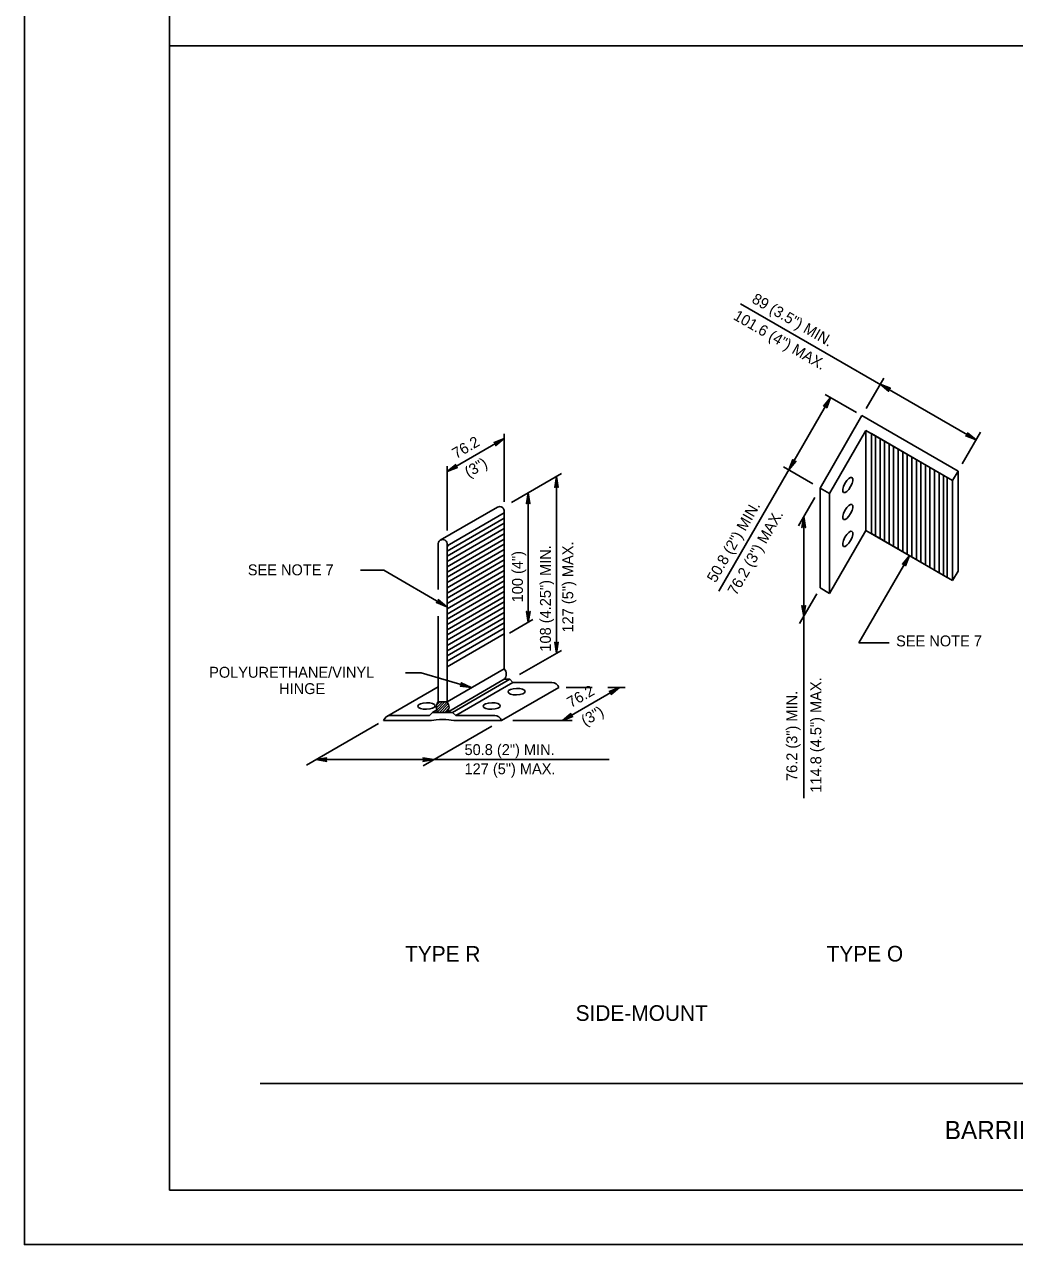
# Model space of a CAD drawing. Extents: x 640253 to 641999, y 298458 to 299646.
# Drawn here: x 640253.3 to 640526.1, y 298457.6 to 298793.5 of the extents above; entities that cross this region are included whole.
import ezdxf

# ---------------------------------------------------------------- set-up
doc = ezdxf.new("R2010")
doc.units = 0
for name, color, linetype in [('1', 7, 'Continuous'), ('2', 7, 'Continuous'), ('PLT-BNDY', 7, 'Continuous')]:
    doc.layers.add(name, color=color, linetype=linetype)

msp = doc.modelspace()

# ---------------------------------------------------------------- linework, layer by layer
at = {"layer": '1'}
for p, q in [((640293.31, 299036.63), (640293.31, 298472.63)), ((640293.31, 298787.67), (641079.31, 298787.67)), ((640318.26, 298501.97), (640782.88, 298501.97)), ((641079.31, 298472.63), (640293.31, 298472.63)), ((640293.31, 298472.63), (640879.31, 298472.63))]:
    msp.add_line(p, q, dxfattribs=at)
at = {"layer": '2'}
for p, q in [((640450.56, 298716.64), (640515.45, 298679.17)), ((640489.99, 298696.18), (640485.17, 298687.84)), ((640475.38, 298690.81), (640444.63, 298637.55)), ((640473.86, 298691.69), (640482.49, 298686.7)), ((640484.01, 298685.83), (640472.51, 298665.91)), ((640510.48, 298670.55), (640484.01, 298685.83)), ((640369.76, 298670.43), (640385.5, 298679.52)), ((640385.5, 298662.1), (640385.5, 298680.83)), ((640485.11, 298681.73), (640475.11, 298664.41)), ((640508.98, 298667.95), (640485.11, 298681.73)), ((640485.11, 298681.73), (640485.11, 298654.23)), ((640487.74, 298680.21), (640487.74, 298652.71)), ((640488.99, 298679.49), (640488.99, 298651.99)), ((640516.7, 298681.32), (640511.64, 298672.56)), ((640490.24, 298678.77), (640490.24, 298651.27)), ((640491.49, 298678.05), (640491.49, 298650.55)), ((640492.74, 298677.32), (640492.74, 298649.83)), ((640493.99, 298676.6), (640493.99, 298649.1)), ((640495.24, 298675.88), (640495.24, 298648.38)), ((640496.49, 298675.16), (640496.49, 298647.66)), ((640497.74, 298674.44), (640497.74, 298646.94)), ((640498.99, 298673.72), (640498.99, 298646.22)), ((640500.24, 298672.99), (640500.24, 298645.5)), ((640369.76, 298654.18), (640369.76, 298671.9)), ((640387.48, 298661.95), (640401.21, 298669.87)), ((640462.36, 298671.77), (640470.52, 298667.06)), ((640501.49, 298672.27), (640501.49, 298644.77)), ((640502.74, 298671.55), (640502.74, 298644.05)), ((640503.99, 298670.83), (640503.99, 298643.33)), ((640505.24, 298670.11), (640505.24, 298642.61)), ((640506.49, 298669.38), (640506.49, 298641.89)), ((640510.48, 298670.55), (640508.98, 298667.95)), ((640510.48, 298670.55), (640510.48, 298643.05)), ((640399.85, 298620.44), (640399.85, 298669.09)), ((640508.98, 298667.95), (640508.98, 298640.45)), ((640392.09, 298628.92), (640392.09, 298664.61)), ((640471.02, 298663.32), (640466.52, 298655.53)), ((640472.51, 298665.91), (640475.11, 298664.41)), ((640472.51, 298665.91), (640472.51, 298638.41)), ((640475.11, 298664.41), (640475.11, 298636.91)), ((640367.87, 298651.54), (640383.62, 298660.63)), ((640385.5, 298659.34), (640385.5, 298616.13)), ((640369.76, 298648.55), (640385.5, 298657.63)), ((640369.76, 298647.1), (640385.5, 298656.19)), ((640467.96, 298658.03), (640467.96, 298580.49)), ((640369.76, 298645.66), (640385.5, 298654.75)), ((640369.76, 298644.22), (640385.5, 298653.3)), ((640485.11, 298654.23), (640475.11, 298636.91)), ((640508.98, 298640.45), (640485.11, 298654.23)), ((640367.26, 298637.98), (640367.26, 298650.25)), ((640369.76, 298642.77), (640385.5, 298651.86)), ((640369.76, 298641.33), (640385.5, 298650.42)), ((640369.76, 298650.25), (640369.76, 298607.04)), ((640369.76, 298649.71), (640369.99, 298650.11)), ((640369.76, 298649.75), (640369.95, 298650.09)), ((640369.76, 298639.89), (640385.5, 298648.97)), ((640369.76, 298638.44), (640385.5, 298647.53)), ((640369.76, 298637), (640385.5, 298646.09)), ((640497.06, 298647.33), (640483.19, 298623.3)), ((640352.35, 298643.33), (640345.91, 298643.33)), ((640369.63, 298633.22), (640352.35, 298643.33)), ((640369.76, 298635.56), (640385.5, 298644.64)), ((640369.76, 298634.11), (640385.5, 298643.2)), ((640510.48, 298643.05), (640508.98, 298640.45)), ((640369.76, 298632.67), (640385.5, 298641.76)), ((640369.76, 298631.22), (640385.5, 298640.31)), ((640369.76, 298629.78), (640385.5, 298638.87)), ((640369.76, 298628.34), (640385.5, 298637.43)), ((640369.76, 298626.9), (640385.5, 298635.98)), ((640471.54, 298636.74), (640466.84, 298628.59)), ((640472.51, 298638.41), (640475.11, 298636.91)), ((640369.76, 298625.45), (640385.5, 298634.54)), ((640369.76, 298624.01), (640385.5, 298633.1)), ((640367.26, 298607.04), (640367.26, 298630.65)), ((640369.76, 298622.56), (640385.5, 298631.65)), ((640369.76, 298621.12), (640385.5, 298630.21)), ((640386.97, 298625.96), (640393.4, 298629.67)), ((640369.76, 298619.68), (640385.5, 298628.77)), ((640369.76, 298618.24), (640385.5, 298627.32)), ((640491.5, 298623.3), (640483.19, 298623.3)), ((640389.66, 298614.56), (640401.21, 298621.22)), ((640369.76, 298607.04), (640385.5, 298616.13)), ((640362.57, 298615.03), (640358.24, 298615.03)), ((640376.36, 298610.99), (640362.57, 298615.03)), ((640385.5, 298613.24), (640369.76, 298604.15)), ((640371.26, 298604.15), (640387, 298613.24)), ((640372.13, 298603.27), (640387.88, 298612.37)), ((640385.5, 298613.24), (640387, 298613.24)), ((640387, 298613.24), (640387.88, 298612.37)), ((640387.88, 298612.37), (640398.6, 298612.37)), ((640353.17, 298603.01), (640367.26, 298611.14)), ((640384.75, 298601.9), (640400.5, 298610.99)), ((640401.49, 298601.9), (640417.25, 298610.99)), ((640402.58, 298610.99), (640409.67, 298610.99)), ((640413.99, 298610.99), (640418.79, 298610.99)), ((640366.78, 298605.37), (640368.45, 298607.04)), ((640366.85, 298606.14), (640367.74, 298607.04)), ((640366.91, 298604.79), (640369.16, 298607.04)), ((640367.14, 298604.32), (640369.8, 298606.97)), ((640367.26, 298607.04), (640369.76, 298607.04)), ((640367.68, 298604.15), (640370.07, 298606.54)), ((640368.39, 298604.15), (640370.22, 298605.99)), ((640354.16, 298603.27), (640364.88, 298603.27)), ((640365.76, 298604.15), (640364.88, 298603.27)), ((640365.76, 298604.15), (640366.88, 298604.8)), ((640365.76, 298604.15), (640371.26, 298604.15)), ((640369.1, 298604.15), (640370.23, 298605.29)), ((640369.76, 298604.15), (640369.76, 298604.15)), ((640371.26, 298604.15), (640372.13, 298603.27)), ((640372.13, 298603.27), (640382.85, 298603.27)), ((640331.01, 298589.63), (640350.88, 298601.1)), ((640352.26, 298601.9), (640364.16, 298601.9)), ((640363.15, 298589.43), (640382.07, 298600.35)), ((640372.86, 298601.9), (640384.75, 298601.9)), ((640387.83, 298601.9), (640404.22, 298601.9)), ((640333.6, 298591.13), (640414.34, 298591.13))]:
    msp.add_line(p, q, dxfattribs=at)
for points in [[(640491.28, 298692.71), (640491.29, 298692.94), (640488.99, 298694.45), (640491.28, 298692.71), (640491.35, 298692.53), (640488.99, 298694.45), (640491.44, 298693.19), (640491.62, 298693.32), (640488.99, 298694.45), (640491.83, 298693.36), (640491.62, 298693.32)], [(640473.64, 298688.52), (640473.87, 298688.51), (640475.38, 298690.81), (640473.64, 298688.52), (640473.46, 298688.46), (640475.38, 298690.81), (640474.12, 298688.37), (640474.25, 298688.18), (640475.38, 298690.81), (640474.29, 298687.98), (640474.25, 298688.18)], [(640382.85, 298678.41), (640383.04, 298678.28), (640385.5, 298679.52), (640382.85, 298678.41), (640382.66, 298678.44), (640385.5, 298679.52), (640383.19, 298678.03), (640383.2, 298677.81), (640385.5, 298679.52), (640383.14, 298677.61), (640383.2, 298677.81)], [(640513.16, 298680.91), (640513.15, 298680.68), (640515.45, 298679.17), (640513.16, 298680.91), (640513.1, 298681.09), (640515.45, 298679.17), (640513.01, 298680.43), (640512.82, 298680.3), (640515.45, 298679.17), (640512.62, 298680.26), (640512.82, 298680.3)], [(640465.62, 298673.19), (640465.38, 298673.2), (640463.88, 298670.9), (640465.62, 298673.19), (640465.8, 298673.25), (640463.88, 298670.9), (640465.13, 298673.34), (640465.01, 298673.53), (640463.88, 298670.9), (640464.97, 298673.73), (640465.01, 298673.53)], [(640372.41, 298671.55), (640372.21, 298671.68), (640369.76, 298670.43), (640372.41, 298671.55), (640372.6, 298671.52), (640369.76, 298670.43), (640372.07, 298671.92), (640372.05, 298672.15), (640369.76, 298670.43), (640372.12, 298672.35), (640372.05, 298672.15)], [(640399.5, 298666.24), (640399.7, 298666.34), (640399.85, 298669.09), (640399.5, 298666.24), (640399.37, 298666.09), (640399.85, 298669.09), (640399.99, 298666.35), (640400.19, 298666.25), (640399.85, 298669.09), (640400.33, 298666.09), (640400.19, 298666.25)], [(640391.74, 298661.76), (640391.94, 298661.86), (640392.09, 298664.61), (640391.74, 298661.76), (640391.61, 298661.61), (640392.09, 298664.61), (640392.23, 298661.86), (640392.43, 298661.76), (640392.09, 298664.61), (640392.57, 298661.61), (640392.43, 298661.76)], [(640467.6, 298655.18), (640467.81, 298655.29), (640467.96, 298658.03), (640467.6, 298655.18), (640467.48, 298655.03), (640467.96, 298658.03), (640468.1, 298655.29), (640468.3, 298655.19), (640467.96, 298658.03), (640468.44, 298655.03), (640468.3, 298655.19)], [(640495.33, 298645.04), (640495.56, 298645.03), (640497.06, 298647.33), (640495.33, 298645.04), (640495.15, 298644.97), (640497.06, 298647.33), (640495.81, 298644.88), (640495.94, 298644.7), (640497.06, 298647.33), (640495.98, 298644.49), (640495.94, 298644.7)], [(640367.36, 298634.99), (640367.34, 298634.76), (640369.63, 298633.22), (640367.36, 298634.99), (640367.3, 298635.17), (640369.63, 298633.22), (640367.2, 298634.51), (640367.01, 298634.38), (640369.63, 298633.22), (640366.8, 298634.35), (640367.01, 298634.38)], [(640468.32, 298633.39), (640468.11, 298633.28), (640467.96, 298630.53), (640468.32, 298633.39), (640468.45, 298633.53), (640467.96, 298630.53), (640467.83, 298633.28), (640467.62, 298633.38), (640467.96, 298630.53), (640467.49, 298633.53), (640467.62, 298633.38)], [(640392.45, 298631.77), (640392.25, 298631.66), (640392.09, 298628.92), (640392.45, 298631.77), (640392.58, 298631.92), (640392.09, 298628.92), (640391.96, 298631.66), (640391.75, 298631.76), (640392.09, 298628.92), (640391.62, 298631.92), (640391.75, 298631.76)], [(640400.21, 298623.29), (640400.01, 298623.19), (640399.85, 298620.44), (640400.21, 298623.29), (640400.34, 298623.44), (640399.85, 298620.44), (640399.72, 298623.19), (640399.51, 298623.29), (640399.85, 298620.44), (640399.38, 298623.44), (640399.51, 298623.29)], [(640373.72, 298612.13), (640373.77, 298611.9), (640376.36, 298610.99), (640373.72, 298612.13), (640373.62, 298612.29), (640376.36, 298610.99), (640373.69, 298611.62), (640373.54, 298611.45), (640376.36, 298610.99), (640373.35, 298611.37), (640373.54, 298611.45)], [(640414.6, 298609.88), (640414.79, 298609.75), (640417.25, 298610.99), (640414.6, 298609.88), (640414.41, 298609.91), (640417.25, 298610.99), (640414.94, 298609.5), (640414.95, 298609.28), (640417.25, 298610.99), (640414.89, 298609.08), (640414.95, 298609.28)], [(640404.14, 298603.02), (640403.95, 298603.14), (640401.49, 298601.9), (640404.14, 298603.02), (640404.33, 298602.98), (640401.49, 298601.9), (640403.8, 298603.39), (640403.79, 298603.62), (640401.49, 298601.9), (640403.85, 298603.81), (640403.79, 298603.62)], [(640336.46, 298590.77), (640336.35, 298590.98), (640333.6, 298591.13), (640336.46, 298590.77), (640336.6, 298590.65), (640333.6, 298591.13), (640336.35, 298591.26), (640336.45, 298591.47), (640333.6, 298591.13), (640336.6, 298591.61), (640336.45, 298591.47)], [(640363.24, 298591.49), (640363.34, 298591.28), (640366.09, 298591.13), (640363.24, 298591.49), (640363.09, 298591.61), (640366.09, 298591.13), (640363.35, 298590.99), (640363.25, 298590.79), (640366.09, 298591.13), (640363.09, 298590.65), (640363.25, 298590.79)]]:
    msp.add_lwpolyline(points, dxfattribs=at)
for points in [[(640486.61, 298680.87), (640507.52, 298668.79), (640507.52, 298641.29), (640486.61, 298653.37)], [(640369.76, 298616.71), (640369.76, 298649.98), (640385.5, 298659.07), (640385.5, 298625.8)]]:
    msp.add_lwpolyline(points, close=True, dxfattribs=at)
for centre, radius, start, end in [((640384.25, 298659.54), 1.26, 350.9133, 119.9792), ((640368.51, 298650.45), 1.26, 350.9133, 189.0867), ((640383.72, 298614.69), 2.29, 320.9923, 39.0623), ((640398.6, 298610.37), 2, 18.187, 90), ((640369.04, 298605.59), 2.29, 140.9377, 219.0623), ((640367.98, 298605.59), 2.29, 320.9923, 39.0623), ((640354.16, 298601.27), 2, 90, 161.79), ((640368.51, 298589.7), 12.5, 81.9962, 98.0038), ((640382.85, 298601.27), 2, 18.21, 90), ((640364.16, 298620.65), 18.75, 270, 278.0038), ((640372.86, 298620.65), 18.75, 261.9962, 270)]:
    msp.add_arc(centre, radius, start, end, dxfattribs=at)
for centre, major_axis in [((640480.11, 298666.73), (-1.14, -2.07)), ((640480.11, 298659.32), (-1.14, -2.07)), ((640480.11, 298651.91), (-1.14, -2.07)), ((640388.88, 298609.85), (2.36, 0.05)), ((640364.07, 298605.9), (2.36, 0.05)), ((640382.04, 298605.9), (2.36, 0.05))]:
    msp.add_ellipse(centre, major_axis=major_axis, ratio=0.379302, dxfattribs=at)
at = {"layer": 'PLT-BNDY'}
msp.add_lwpolyline([(640253.31, 299051.63), (641094.31, 299051.63), (641094.31, 298457.63), (640253.31, 298457.63)], close=True, dxfattribs=at)

# ---------------------------------------------------------------- texts
at = {"layer": '2'}
for s, rotation, p in [('89 (3.5") MIN.', 329.9989, (640453.42, 298717.12)), ('101.6 (4") MAX.', 329.9989, (640448.35, 298712.48)), ('76.2', 30, (640372.23, 298673.85)), ('(3")', 30, (640375.67, 298668.7)), ('50.8 (2") MIN.', 59.9989, (640443.7, 298639.64)), ('76.2 (3") MAX.', 59.9989, (640449.38, 298636.13)), ('108 (4.25") MIN.', 90, (640398.32, 298620.87)), ('127 (5") MAX.', 90, (640404.48, 298626.13)), ('100 (4")', 90, (640390.62, 298634.43)), ('114.8 (4.5") MAX.', 89.9989, (640472.83, 298582.03)), ('76.2', 30, (640403.87, 298605.32)), ('76.2 (3") MIN.', 89.9989, (640466.19, 298585.24)), ('(3")', 30, (640407.75, 298600.32))]:
    msp.add_text(s, height=3, rotation=rotation, dxfattribs=at).set_placement(p)
for s, height, p in [('SEE NOTE 7', 3, (640314.85, 298641.88)), ('SEE NOTE 7', 3, (640493.42, 298622.31)), ('POLYURETHANE/VINYL', 3, (640304.2, 298613.68)), ('HINGE', 3, (640323.48, 298609.18)), ('50.8 (2") MIN.', 3, (640374.54, 298592.39)), ('127 (5") MAX.', 3, (640374.54, 298587.11)), ('TYPE R', 4.3, (640358.16, 298535.5)), ('TYPE O', 4.3, (640474.27, 298535.56)), ('SIDE-MOUNT', 4.3, (640405.14, 298519.22)), ('BARRIER DELINEATORS', 5, (640506.83, 298486.66))]:
    msp.add_text(s, height=height, dxfattribs=at).set_placement(p)

doc.saveas('drawing.dxf')
